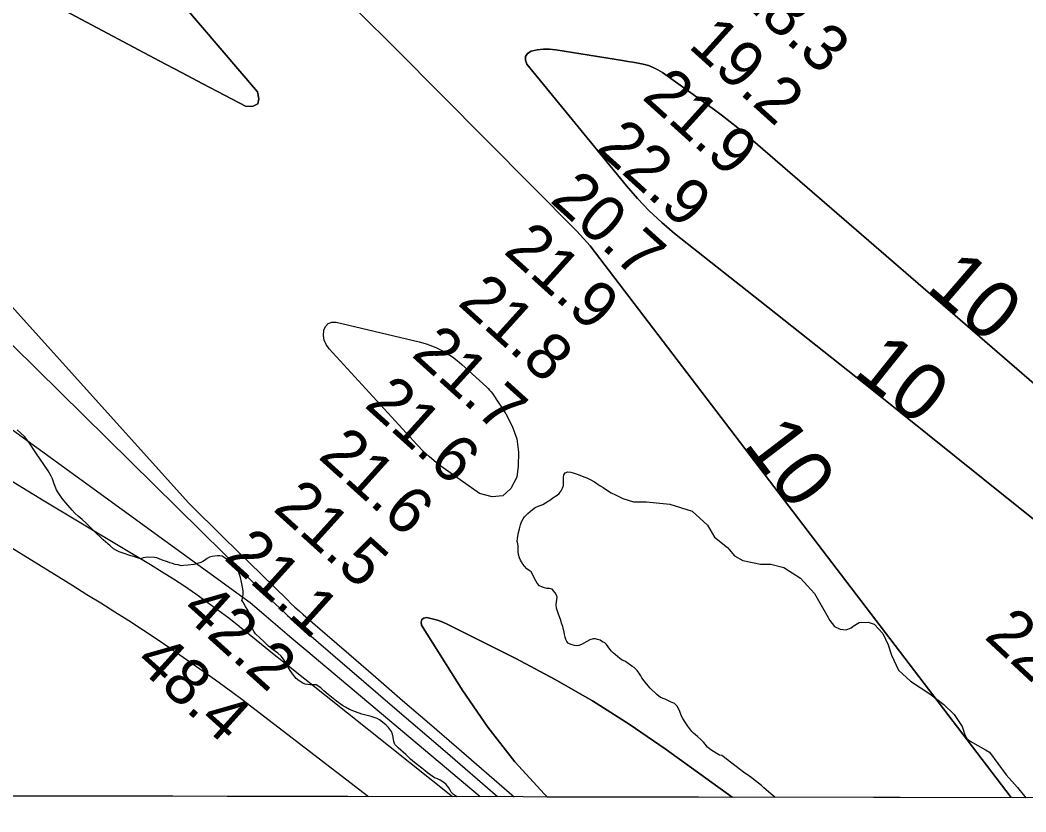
# Model space of a CAD drawing. Extents: x 3192986 to 3230865, y 867483 to 892886.
# Drawn here: x 3216217 to 3217672, y 872862 to 874007 of the extents above; entities that cross this region are included whole.
import ezdxf

# ---------------------------------------------------------------- set-up
doc = ezdxf.new("R2010")
doc.units = 0
for name, color, linetype in [('V-GRID-FRAM', 7, 'Continuous'), ('V-RIVR-RANG', 7, 'Continuous'), ('V-SITE-VEGE', 7, 'Continuous'), ('V-TOPO-DPTH', 7, 'Continuous'), ('V-TOPO-MAJR', 7, 'Continuous'), ('V-TOPO-MINR', 7, 'Continuous'), ('V-TOPO-MINR-IDEN', 7, 'Continuous')]:
    doc.layers.add(name, color=color, linetype=linetype)

msp = doc.modelspace()

# ---------------------------------------------------------------- linework, layer by layer
at = {"layer": 'V-GRID-FRAM'}
msp.add_lwpolyline([(3197229, 891108.8), (3228580.6, 891049.6), (3228554.1, 872861.6), (3197186.7, 872920.9)], dxfattribs=at)
at = {"layer": 'V-SITE-VEGE'}
for p, q in [((3216223.6, 873404.7), (3216212.9, 873414.3)), ((3216229.7, 873396.6), (3216223.6, 873404.7)), ((3216239.9, 873381), (3216229.7, 873396.6)), ((3216257.6, 873355.1), (3216239.9, 873381)), ((3216262, 873347.4), (3216257.6, 873355.1)), ((3216263.9, 873343.5), (3216262, 873347.4)), ((3217003.2, 873345.4), (3217003.9, 873349.2)), ((3217003.9, 873349.2), (3217005.8, 873352.3)), ((3217005.8, 873352.3), (3217009.4, 873353.7)), ((3217009.4, 873353.7), (3217014.1, 873353)), ((3217014.1, 873353), (3217019, 873351.9)), ((3217019, 873351.9), (3217024.5, 873350)), ((3217024.5, 873350), (3217030.1, 873347.4)), ((3217030.1, 873347.4), (3217034, 873346.1)), ((3216265.2, 873340.5), (3216263.9, 873343.5)), ((3216266, 873337.2), (3216265.2, 873340.5)), ((3216269.7, 873327.8), (3216266, 873337.2)), ((3217002, 873329.8), (3217003.2, 873333.8)), ((3217003.4, 873342.2), (3217003.2, 873345.4)), ((3217003.2, 873333.8), (3217003.5, 873337.3)), ((3217003.5, 873337.3), (3217003.4, 873342.2)), ((3217034, 873346.1), (3217037.3, 873344.9)), ((3217037.3, 873344.9), (3217042.1, 873342.6)), ((3217042.1, 873342.6), (3217048, 873339.2)), ((3217048, 873339.2), (3217056.3, 873333.6)), ((3217056.3, 873333.6), (3217060.9, 873330.8)), ((3216271.4, 873325.1), (3216269.7, 873327.8)), ((3216278.1, 873315.3), (3216271.4, 873325.1)), ((3216988.1, 873315.9), (3216994.3, 873319.7)), ((3216994.3, 873319.7), (3216997.1, 873322.3)), ((3216997.1, 873322.3), (3216999.9, 873326.1)), ((3216999.9, 873326.1), (3217002, 873329.8)), ((3217060.9, 873330.8), (3217067.1, 873326.6)), ((3217067.1, 873326.6), (3217072.2, 873323.5)), ((3217072.2, 873323.5), (3217078.4, 873320.2)), ((3217078.4, 873320.2), (3217089.1, 873315)), ((3216283.1, 873308.8), (3216278.1, 873315.3)), ((3216292.4, 873298), (3216283.1, 873308.8)), ((3216962.3, 873301.9), (3216965.5, 873303.7)), ((3216965.5, 873303.7), (3216973.2, 873306.4)), ((3216973.2, 873306.4), (3216984.9, 873313.4)), ((3216984.9, 873313.4), (3216988.1, 873315.9)), ((3217089.1, 873315), (3217104.6, 873310.3)), ((3217104.6, 873310.3), (3217123.3, 873310.3)), ((3217123.3, 873310.3), (3217157.3, 873306.9)), ((3217157.3, 873306.9), (3217189.6, 873296.7)), ((3216296.2, 873294.1), (3216292.4, 873298)), ((3216301.2, 873289.5), (3216296.2, 873294.1)), ((3216306.8, 873284.8), (3216301.2, 873289.5)), ((3216944.9, 873285.5), (3216947, 873288.6)), ((3216947, 873288.6), (3216951.5, 873293.2)), ((3216951.5, 873293.2), (3216958.6, 873299.4)), ((3216958.6, 873299.4), (3216962.3, 873301.9)), ((3217189.6, 873296.7), (3217211.7, 873276.3)), ((3216312.9, 873279.2), (3216306.8, 873284.8)), ((3216323.2, 873268.9), (3216312.9, 873279.2)), ((3216939.5, 873271.2), (3216941.3, 873276.8)), ((3216941.3, 873276.8), (3216942.8, 873281.1)), ((3216942.8, 873281.1), (3216944.9, 873285.5)), ((3217211.7, 873276.3), (3217221.9, 873259.3)), ((3216337.4, 873255.2), (3216323.2, 873268.9)), ((3216936.6, 873257.7), (3216938.1, 873266.1)), ((3216938.1, 873266.1), (3216939.5, 873271.2)), ((3217221.9, 873259.3), (3217240.6, 873244)), ((3216347.2, 873246.6), (3216337.4, 873255.2)), ((3216352.3, 873242.4), (3216347.2, 873246.6)), ((3216936.5, 873253), (3216936.6, 873257.7)), ((3216937.1, 873249.7), (3216936.5, 873253)), ((3216937.5, 873245.9), (3216937.1, 873249.7)), ((3216937.5, 873238.6), (3216937.5, 873245.9)), ((3216356.6, 873239.8), (3216352.3, 873242.4)), ((3216360.4, 873237.8), (3216356.6, 873239.8)), ((3216366.2, 873235.8), (3216360.4, 873237.8)), ((3216377.5, 873232.1), (3216366.2, 873235.8)), ((3216381.4, 873231.2), (3216377.5, 873232.1)), ((3216388.6, 873228.8), (3216381.4, 873231.2)), ((3216401.6, 873230.2), (3216395.1, 873229.4)), ((3216411.8, 873229.9), (3216401.6, 873230.2)), ((3216495.1, 873231.1), (3216491.1, 873230)), ((3216499.1, 873231.8), (3216495.1, 873231.1)), ((3216502.5, 873232.2), (3216499.1, 873231.8)), ((3216506, 873232), (3216502.5, 873232.2)), ((3216509.3, 873231.4), (3216506, 873232)), ((3216512.3, 873229.9), (3216509.3, 873231.4)), ((3216938.1, 873233.9), (3216937.5, 873238.6)), ((3216939.5, 873229.4), (3216938.1, 873233.9)), ((3217240.6, 873244), (3217250.8, 873232.1)), ((3217250.8, 873232.1), (3217262.7, 873225.3)), ((3216392, 873228), (3216388.6, 873228.8)), ((3216395.1, 873229.4), (3216392, 873228)), ((3216415, 873229.1), (3216411.8, 873229.9)), ((3216418.5, 873227.9), (3216415, 873229.1)), ((3216424.3, 873225.4), (3216418.5, 873227.9)), ((3216427.4, 873224.2), (3216424.3, 873225.4)), ((3216430.5, 873223.2), (3216427.4, 873224.2)), ((3216433.8, 873222.1), (3216430.5, 873223.2)), ((3216437.5, 873220.9), (3216433.8, 873222.1)), ((3216441.3, 873219.8), (3216437.5, 873220.9)), ((3216445.6, 873219), (3216441.3, 873219.8)), ((3216450.2, 873217.7), (3216445.6, 873219)), ((3216453.7, 873217.9), (3216450.2, 873217.7)), ((3216460.2, 873218.8), (3216453.7, 873217.9)), ((3216468.3, 873219.4), (3216460.2, 873218.8)), ((3216474, 873220.9), (3216468.3, 873219.4)), ((3216478.4, 873222.6), (3216474, 873220.9)), ((3216481.4, 873224.1), (3216478.4, 873222.6)), ((3216484.1, 873225.6), (3216481.4, 873224.1)), ((3216487.9, 873228.4), (3216484.1, 873225.6)), ((3216491.1, 873230), (3216487.9, 873228.4)), ((3216515.6, 873227.3), (3216512.3, 873229.9)), ((3216523.3, 873220.5), (3216515.6, 873227.3)), ((3216529.6, 873215.4), (3216523.3, 873220.5)), ((3216941.1, 873225.9), (3216939.5, 873229.4)), ((3216942.5, 873223.2), (3216941.1, 873225.9)), ((3216944.6, 873219.9), (3216942.5, 873223.2)), ((3216946.9, 873217.2), (3216944.6, 873219.9)), ((3216950.3, 873213.5), (3216946.9, 873217.2)), ((3217262.7, 873225.3), (3217288.2, 873220.2)), ((3217288.2, 873220.2), (3217303.5, 873220.2)), ((3217303.5, 873220.2), (3217322.2, 873215.1)), ((3216531.9, 873211.8), (3216529.6, 873215.4)), ((3216533.5, 873208.2), (3216531.9, 873211.8)), ((3216536, 873200.7), (3216533.5, 873208.2)), ((3216953.6, 873210.7), (3216950.3, 873213.5)), ((3216956.5, 873209.2), (3216953.6, 873210.7)), ((3216963.2, 873195.8), (3216956.5, 873209.2)), ((3217322.2, 873215.1), (3217346, 873199.8)), ((3216537.4, 873193.9), (3216536, 873200.7)), ((3216539.1, 873186.6), (3216537.4, 873193.9)), ((3216539.9, 873181.4), (3216539.1, 873186.6)), ((3216965.1, 873192.6), (3216963.2, 873195.8)), ((3216968.5, 873188.7), (3216965.1, 873192.6)), ((3216972.8, 873186.6), (3216968.5, 873188.7)), ((3216975.8, 873185.6), (3216972.8, 873186.6)), ((3217346, 873199.8), (3217366.4, 873177.7)), ((3216538, 873167.7), (3216539.2, 873172.1)), ((3216539.2, 873172.1), (3216540.1, 873177.3)), ((3216540.1, 873177.3), (3216539.9, 873181.4)), ((3216979.2, 873184.7), (3216975.8, 873185.6)), ((3216982.9, 873184.8), (3216979.2, 873184.7)), ((3216986.8, 873183.7), (3216982.9, 873184.8)), ((3216989.1, 873181.5), (3216986.8, 873183.7)), ((3216991.4, 873178.8), (3216989.1, 873181.5)), ((3216993.3, 873175.3), (3216991.4, 873178.8)), ((3216994.2, 873172.3), (3216993.3, 873175.3)), ((3216993.8, 873169), (3216994.2, 873172.3)), ((3217366.4, 873177.7), (3217380, 873153.8)), ((3216539.8, 873165.2), (3216538, 873167.7)), ((3216543.3, 873158.9), (3216539.8, 873165.2)), ((3216545.6, 873155.1), (3216543.3, 873158.9)), ((3216992.7, 873161.2), (3216993, 873165.7)), ((3216993.3, 873156.4), (3216992.7, 873161.2)), ((3216993, 873165.7), (3216993.8, 873169)), ((3216547.4, 873151.5), (3216545.6, 873155.1)), ((3216548.8, 873147.9), (3216547.4, 873151.5)), ((3216549.9, 873144.5), (3216548.8, 873147.9)), ((3216550.5, 873141.5), (3216549.9, 873144.5)), ((3216996.1, 873147.9), (3216993.3, 873156.4)), ((3216999.4, 873139.2), (3216996.1, 873147.9)), ((3217380, 873153.8), (3217388.5, 873138.5)), ((3216551.4, 873133.1), (3216550.5, 873141.5)), ((3216552.4, 873129), (3216551.4, 873133.1)), ((3216553.7, 873125.5), (3216552.4, 873129)), ((3217000.6, 873134.5), (3216999.4, 873139.2)), ((3217002.2, 873130), (3217000.6, 873134.5)), ((3217004.4, 873121.8), (3217002.2, 873130)), ((3217388.5, 873138.5), (3217395.3, 873130)), ((3217395.3, 873130), (3217403.6, 873126.2)), ((3217419.3, 873127.8), (3217422.4, 873130.1)), ((3217422.4, 873130.1), (3217431, 873135.6)), ((3217431, 873135.6), (3217444.3, 873136)), ((3217444.3, 873136), (3217453, 873133.3)), ((3217453, 873133.3), (3217465.5, 873119.6)), ((3216555.6, 873122.1), (3216553.7, 873125.5)), ((3216557.8, 873119.4), (3216555.6, 873122.1)), ((3216564.2, 873113.6), (3216557.8, 873119.4)), ((3217004.8, 873118.4), (3217004.4, 873121.8)), ((3217005.7, 873114.4), (3217004.8, 873118.4)), ((3217006.8, 873111), (3217005.7, 873114.4)), ((3217403.6, 873126.2), (3217412.3, 873124.9)), ((3217412.3, 873124.9), (3217419.3, 873127.8)), ((3217465.5, 873119.6), (3217472.9, 873103.5)), ((3216569.6, 873108), (3216564.2, 873113.6)), ((3216576.6, 873101.5), (3216569.6, 873108)), ((3216583.2, 873095.9), (3216576.6, 873101.5)), ((3217008.1, 873108), (3217006.8, 873111)), ((3217010.3, 873105.8), (3217008.1, 873108)), ((3217013, 873104.3), (3217010.3, 873105.8)), ((3217016.1, 873103.2), (3217013, 873104.3)), ((3217019.2, 873102.5), (3217016.1, 873103.2)), ((3217022.4, 873102.1), (3217019.2, 873102.5)), ((3217025.5, 873102.5), (3217022.4, 873102.1)), ((3217029.2, 873103.9), (3217025.5, 873102.5)), ((3217037.3, 873108.1), (3217029.2, 873103.9)), ((3217041.4, 873110.5), (3217037.3, 873108.1)), ((3217046.4, 873112.1), (3217041.4, 873110.5)), ((3217049.6, 873111.8), (3217046.4, 873112.1)), ((3217052.6, 873111.1), (3217049.6, 873111.8)), ((3217056.2, 873109.9), (3217052.6, 873111.1)), ((3217059.8, 873107.8), (3217056.2, 873109.9)), ((3217062.9, 873106.3), (3217059.8, 873107.8)), ((3217065.5, 873103.7), (3217062.9, 873106.3)), ((3217070.2, 873097.2), (3217065.5, 873103.7)), ((3217472.9, 873103.5), (3217478, 873088.2)), ((3216589.8, 873091.2), (3216583.2, 873095.9)), ((3216594.7, 873086.7), (3216589.8, 873091.2)), ((3216598, 873082.5), (3216594.7, 873086.7)), ((3217072.8, 873094.1), (3217070.2, 873097.2)), ((3217075.7, 873091.4), (3217072.8, 873094.1)), ((3217078.3, 873089.4), (3217075.7, 873091.4)), ((3217084.9, 873083.4), (3217078.3, 873089.4)), ((3217478, 873088.2), (3217488.2, 873066.7)), ((3216608, 873066.1), (3216598, 873082.5)), ((3217088.3, 873081.2), (3217084.9, 873083.4)), ((3217091.9, 873079.6), (3217088.3, 873081.2)), ((3217094.9, 873077.6), (3217091.9, 873079.6)), ((3217102, 873072.3), (3217094.9, 873077.6)), ((3217105.5, 873070.3), (3217102, 873072.3)), ((3217109.7, 873066.4), (3217105.5, 873070.3)), ((3216612.5, 873059.2), (3216608, 873066.1)), ((3216616.4, 873054.8), (3216612.5, 873059.2)), ((3217112.3, 873063), (3217109.7, 873066.4)), ((3217115.2, 873058.5), (3217112.3, 873063)), ((3217116.8, 873055.6), (3217115.2, 873058.5)), ((3217123.3, 873047), (3217116.8, 873055.6)), ((3217488.2, 873066.7), (3217505.4, 873050.6)), ((3216620.7, 873051), (3216616.4, 873054.8)), ((3216626.2, 873047.7), (3216620.7, 873051)), ((3216629.8, 873046.4), (3216626.2, 873047.7)), ((3216633.2, 873045.8), (3216629.8, 873046.4)), ((3216636.8, 873045.5), (3216633.2, 873045.8)), ((3216642.2, 873045.6), (3216636.8, 873045.5)), ((3216645.4, 873045.3), (3216642.2, 873045.6)), ((3216652.1, 873041.1), (3216645.4, 873045.3)), ((3216656.8, 873036.7), (3216652.1, 873041.1)), ((3217128.8, 873040.8), (3217123.3, 873047)), ((3217505.4, 873050.6), (3217533.5, 873032.3)), ((3216662.9, 873031.4), (3216656.8, 873036.7)), ((3216675.1, 873021.8), (3216662.9, 873031.4)), ((3217138.4, 873031.3), (3217128.8, 873040.8)), ((3217143.8, 873027.2), (3217138.4, 873031.3)), ((3217150.2, 873024.6), (3217143.8, 873027.2)), ((3217533.5, 873032.3), (3217553.6, 873017.1)), ((3216683.7, 873015.5), (3216675.1, 873021.8)), ((3216687.9, 873012.9), (3216683.7, 873015.5)), ((3216693.8, 873009.8), (3216687.9, 873012.9)), ((3217158.1, 873020.6), (3217150.2, 873024.6)), ((3217163.8, 873018.2), (3217158.1, 873020.6)), ((3217167.6, 873014.8), (3217163.8, 873018.2)), ((3217170.3, 873010.1), (3217167.6, 873014.8)), ((3217553.6, 873017.1), (3217568.8, 873002.4)), ((3216702.3, 873006.4), (3216693.8, 873009.8)), ((3216711.6, 873003.1), (3216702.3, 873006.4)), ((3216725.2, 872999.5), (3216711.6, 873003.1)), ((3216733.7, 872996.6), (3216725.2, 872999.5)), ((3217171.7, 873006.9), (3217170.3, 873010.1)), ((3217174.2, 873000.1), (3217171.7, 873006.9)), ((3217176, 872996.6), (3217174.2, 873000.1)), ((3217568.8, 873002.4), (3217580, 872985.1)), ((3216737, 872995), (3216733.7, 872996.6)), ((3216744, 872989.7), (3216737, 872995)), ((3216746.8, 872987.3), (3216744, 872989.7)), ((3216750.3, 872983.8), (3216746.8, 872987.3)), ((3216754.3, 872977.7), (3216750.3, 872983.8)), ((3217179.4, 872991.2), (3217176, 872996.6)), ((3217183.4, 872985.5), (3217179.4, 872991.2)), ((3217189.1, 872978.1), (3217183.4, 872985.5)), ((3217580, 872985.1), (3217584, 872973.1)), ((3216755.7, 872974.1), (3216754.3, 872977.7)), ((3216757, 872969.8), (3216755.7, 872974.1)), ((3216757.7, 872963.6), (3216757, 872969.8)), ((3217191.3, 872975.5), (3217189.1, 872978.1)), ((3217197.2, 872970.6), (3217191.3, 872975.5)), ((3217202.3, 872966), (3217197.2, 872970.6)), ((3217584, 872973.1), (3217587.1, 872968)), ((3216759.2, 872958.9), (3216757.7, 872963.6)), ((3216761.7, 872956.7), (3216759.2, 872958.9)), ((3216764.3, 872954.1), (3216761.7, 872956.7)), ((3216775, 872944.6), (3216764.3, 872954.1)), ((3217206.2, 872962.1), (3217202.3, 872966)), ((3217208.4, 872959.6), (3217206.2, 872962.1)), ((3217211.7, 872955.4), (3217208.4, 872959.6)), ((3217213.9, 872953.4), (3217211.7, 872955.4)), ((3217587.1, 872968), (3217591.8, 872964.1)), ((3217591.8, 872964.1), (3217613.7, 872951.5)), ((3216781.9, 872938), (3216775, 872944.6)), ((3217216.6, 872951.3), (3217213.9, 872953.4)), ((3217224.3, 872946.4), (3217216.6, 872951.3)), ((3217228.8, 872943.8), (3217224.3, 872946.4)), ((3217232.2, 872943.2), (3217228.8, 872943.8)), ((3217246.7, 872932), (3217232.2, 872943.2)), ((3217613.7, 872951.5), (3217619.6, 872948)), ((3217619.6, 872948), (3217644, 872915.3)), ((3216787.9, 872933.1), (3216781.9, 872938)), ((3216798.5, 872924.9), (3216787.9, 872933.1)), ((3216803.2, 872920.8), (3216798.5, 872924.9)), ((3217257.6, 872924.1), (3217246.7, 872932)), ((3216806.7, 872918.1), (3216803.2, 872920.8)), ((3216809.7, 872915.5), (3216806.7, 872918.1)), ((3216816.8, 872911), (3216809.7, 872915.5)), ((3216820.3, 872909.7), (3216816.8, 872911)), ((3217263.8, 872919.2), (3217257.6, 872924.1)), ((3217267.1, 872916.8), (3217263.8, 872919.2)), ((3217272.4, 872913.4), (3217267.1, 872916.8)), ((3217289.7, 872899.8), (3217272.4, 872913.4)), ((3217644, 872915.3), (3217660, 872896.7)), ((3216824.9, 872907.7), (3216820.3, 872909.7)), ((3216830, 872904.2), (3216824.9, 872907.7)), ((3216833.4, 872901), (3216830, 872904.2)), ((3216837.2, 872896.4), (3216833.4, 872901)), ((3216839.3, 872893.2), (3216837.2, 872896.4)), ((3217293.2, 872896.4), (3217289.7, 872899.8)), ((3217303.2, 872887.6), (3217293.2, 872896.4)), ((3217660, 872896.7), (3217672.2, 872882.1)), ((3214790, 872887.6), (3216848.6, 872883.7)), ((3216841, 872890.1), (3216839.3, 872893.2)), ((3216844.4, 872886.8), (3216841, 872890.1)), ((3216848.6, 872883.7), (3216844.4, 872886.8)), ((3217309, 872882.8), (3217303.2, 872887.6)), ((3217672.2, 872882.1), (3217309, 872882.8))]:
    msp.add_line(p, q, dxfattribs=at)
at = {"layer": 'V-TOPO-DPTH'}
for points in [[(3216344.5, 874156.6), (3216560.7, 873903.4), (3216562.6, 873893.3), (3216561, 873886), (3216554.2, 873882.8), (3216544, 873882.4), (3216512.8, 873898.7), (3216481.6, 873915.1), (3216450.4, 873931.5), (3216419.3, 873948.1), (3216222.7, 874052.9)], [(3217651.2, 872882.2), (3217042, 873680.5), (3217022.6, 873702), (3216761.3, 873965.2), (3216705.6, 874020.4)], [(3217827.2, 873357.7), (3217266.7, 873842.3), (3217255.8, 873851.4), (3217244.7, 873860.4), (3217233.4, 873869), (3217222, 873877.4), (3217146.4, 873931.5), (3217139.9, 873935.5), (3217133.2, 873938.9), (3217126.2, 873941.5), (3217118.8, 873943.4), (3217111.3, 873944.9), (3217103.8, 873946.3), (3217096.2, 873947.6), (3217088.6, 873948.9), (3216992.3, 873964.2), (3216983.3, 873965.1), (3216974.4, 873965.2), (3216965.4, 873964.2), (3216956.6, 873962.4), (3216951.4, 873958.9), (3216948.4, 873954.7), (3216948.4, 873949.5), (3216950.5, 873943.6), (3217094.3, 873767.6), (3217110.5, 873749.1), (3217127.4, 873731.3), (3217145.4, 873714.7), (3217164.1, 873698.8), (3217287.4, 873601.1), (3217368.4, 873536.9), (3217449.2, 873472.6), (3217530, 873408.2), (3217610.7, 873343.7), (3217782.9, 873205.8)], [(3216821.1, 873138.9), (3216813.4, 873141.1), (3216805.5, 873142.9), (3216801.1, 873141.8), (3216798.2, 873139.8), (3216797.4, 873136.3), (3216798.1, 873131.9), (3216857.7, 873036.9), (3216893.9, 872984.3), (3216932.8, 872933.9), (3216975.9, 872887.1), (3216979.6, 872883.5)], [(3216979.6, 872883.5), (3217247.5, 872882.9), (3217150.4, 872952.9), (3217098.3, 872988.5), (3217045.1, 873022.5), (3216990.4, 873053.8), (3216934.6, 873083.4), (3216836.1, 873132.8), (3216828.7, 873136.1), (3216821.1, 873138.9)], [(3218146.8, 872881.2), (3217651.2, 872882.2)]]:
    msp.add_lwpolyline(points, dxfattribs=at)
at = {"layer": 'V-TOPO-MAJR'}
msp.add_lwpolyline([(3215270, 874297.9), (3215545.1, 873988.1), (3215593.4, 873934.6), (3215642.4, 873881.8), (3215692.4, 873829.8), (3215743, 873778.5), (3215822.7, 873699), (3215834.2, 873688.1), (3215845.9, 873677.6), (3215858, 873667.6), (3215870.5, 873657.9), (3216549.8, 873164.8), (3216569.9, 873147.5), (3216590, 873130.2), (3216610.3, 873113.1), (3216630.5, 873096), (3216882.8, 872883.6)], dxfattribs=at)
at = {"layer": 'V-TOPO-MINR'}
for points in [[(3214960.6, 874923.9), (3215403.5, 874495.4), (3215414.3, 874484.8), (3215425.1, 874474.2), (3215435.8, 874463.4), (3215446.4, 874452.6), (3216003.3, 873736.7), (3216580.5, 873167.9), (3216592.2, 873156.8), (3216604.1, 873145.9), (3216616.1, 873135.1), (3216628.3, 873124.5), (3216755.9, 873014.8), (3216831.9, 872949.3), (3216907.7, 872883.7), (3216907.9, 872883.6)], [(3215243.1, 874685.4), (3215402, 874531), (3215421.6, 874511.8), (3215441.1, 874492.5), (3215460.4, 874473.1), (3215479.6, 874453.5), (3215940.4, 873893.6), (3215946.3, 873885.7), (3215977.1, 873846.7), (3215983.5, 873838.8), (3216460.9, 873309), (3216511.8, 873258.2), (3216603.3, 873168.8), (3216609, 873163.3), (3216614.8, 873157.9), (3216620.8, 873152.5), (3216626.7, 873147.3), (3216692.6, 873090.3), (3216731.6, 873056.6), (3216770.5, 873022.9), (3216809.5, 872989.3), (3216848.5, 872955.6), (3216931.8, 872883.5)], [(3216222.7, 874052.9), (3216419.3, 873948.1), (3216450.4, 873931.5), (3216481.6, 873915.1), (3216512.8, 873898.7), (3216544, 873882.4), (3216554.2, 873882.8), (3216561, 873886), (3216562.6, 873893.3), (3216560.7, 873903.4), (3216344.5, 874156.6)], [(3216705.6, 874020.4), (3216761.3, 873965.2), (3217022.6, 873702), (3217042, 873680.5), (3217651.2, 872882.2)], [(3217782.9, 873205.8), (3217610.7, 873343.7), (3217530, 873408.2), (3217449.2, 873472.6), (3217368.4, 873536.9), (3217287.4, 873601.1), (3217164.1, 873698.8), (3217145.4, 873714.7), (3217127.4, 873731.3), (3217110.5, 873749.1), (3217094.3, 873767.6), (3216950.5, 873943.6), (3216948.4, 873949.5), (3216948.4, 873954.7), (3216951.4, 873958.9), (3216956.6, 873962.4), (3216965.4, 873964.2), (3216974.4, 873965.2), (3216983.3, 873965.1), (3216992.3, 873964.2), (3217088.6, 873948.9), (3217096.2, 873947.6), (3217103.8, 873946.3), (3217111.3, 873944.9), (3217118.8, 873943.4), (3217126.2, 873941.5), (3217133.2, 873938.9), (3217139.9, 873935.5), (3217146.4, 873931.5), (3217222, 873877.4), (3217233.4, 873869), (3217244.7, 873860.4), (3217255.8, 873851.4), (3217266.7, 873842.3), (3217827.2, 873357.7)], [(3216935.8, 873401.5), (3216938.2, 873382.1), (3216937.9, 873362), (3216935.9, 873346.1), (3216927.1, 873329.4), (3216915.6, 873318.8), (3216900, 873317.5), (3216881.7, 873322.3), (3216829.3, 873359.5), (3216819.3, 873367.1), (3216809.6, 873375.2), (3216800.5, 873383.8), (3216791.7, 873392.8), (3216664.2, 873531.7), (3216660.1, 873537.8), (3216657.2, 873544.2), (3216656.2, 873551.2), (3216656.5, 873558.6), (3216659.2, 873564.2), (3216663, 873568.3), (3216668.3, 873570.1), (3216674.6, 873570.3), (3216794.5, 873541.9), (3216803, 873539.5), (3216811.4, 873536.7), (3216819.5, 873533.2), (3216827.5, 873529.3), (3216835.2, 873524.8), (3216842.6, 873520), (3216849.7, 873514.6), (3216856.4, 873508.9), (3216891.9, 873476.7), (3216894.2, 873474.4), (3216896.4, 873472), (3216898.5, 873469.5), (3216900.4, 873466.9), (3216919.9, 873437.8), (3216929.2, 873420), (3216935.8, 873401.5)], [(3216189.6, 873349.6), (3216252, 873311.9), (3216314.4, 873274.3), (3216405.8, 873219.4), (3216422.5, 873209.2), (3216439, 873198.8), (3216455.4, 873188), (3216471.6, 873177), (3216487.5, 873165.7), (3216503.3, 873154.1), (3216518.9, 873142.2), (3216534.3, 873130.1), (3216535.2, 873129.4), (3216550.9, 873116.7), (3216566.6, 873104.1), (3216582.4, 873091.5), (3216598.1, 873078.9), (3216842.6, 872883.7)], [(3216053.7, 873336.6), (3216273, 873201.5), (3216293.3, 873189), (3216313.6, 873176.4), (3216333.9, 873163.9), (3216354.2, 873151.3), (3216374.3, 873138.6), (3216394.4, 873125.6), (3216414.2, 873112.4), (3216433.9, 873098.9), (3216487, 873062), (3216499.8, 873052.9), (3216512.5, 873043.7), (3216525.1, 873034.4), (3216537.7, 873024.9), (3216721.2, 872883.9)], [(3216979.6, 872883.5), (3216975.9, 872887.1), (3216932.8, 872933.9), (3216893.9, 872984.3), (3216857.7, 873036.9), (3216798.1, 873131.9), (3216797.4, 873136.3), (3216798.2, 873139.8), (3216801.1, 873141.8), (3216805.5, 873142.9), (3216813.4, 873141.1), (3216821.1, 873138.9)], [(3216821.1, 873138.9), (3216828.7, 873136.1), (3216836.1, 873132.8), (3216934.6, 873083.4), (3216990.4, 873053.8), (3217045.1, 873022.5), (3217098.3, 872988.5), (3217150.4, 872952.9), (3217247.5, 872882.9)]]:
    msp.add_lwpolyline(points, dxfattribs=at)

# ---------------------------------------------------------------- texts
at = {"layer": 'V-RIVR-RANG'}
for s, rotation, p in [('18.3', 317.9122, (3217249.1, 874043.3)), ('19.2', 317.9122, (3217182.3, 873968.8)), ('21.9', 317.9122, (3217115.4, 873894.6)), ('22.9', 317.9122, (3217048.6, 873820.1)), ('20.7', 317.9122, (3216982.1, 873745.5)), ('21.9', 317.9122, (3216915.1, 873671.2)), ('21.8', 317.9122, (3216848.6, 873596.6)), ('21.7', 317.9122, (3216781.8, 873522.1)), ('21.6', 317.9122, (3216713.7, 873448.9)), ('21.6', 317.9122, (3216646.9, 873374.4)), ('21.5', 317.9122, (3216581.5, 873298.7)), ('21.1', 317.9122, (3216510.5, 873228.2)), ('42.2', 317.9783, (3216448, 873149.7)), ('22.2', 317.1344, (3217610.6, 873113.8)), ('48.4', 317.9783, (3216381.2, 873075.2))]:
    msp.add_text(s, height=67, rotation=rotation, dxfattribs=at).set_placement(p)
at = {"layer": 'V-TOPO-MINR-IDEN'}
for rotation, p in [(319.1565, (3217526.2, 873617.9)), (321.4226, (3217420.8, 873495.3)), (307.3478, (3217261.7, 873392.6))]:
    msp.add_text('10', height=83, rotation=rotation, dxfattribs=at).set_placement(p)

doc.saveas('drawing.dxf')
